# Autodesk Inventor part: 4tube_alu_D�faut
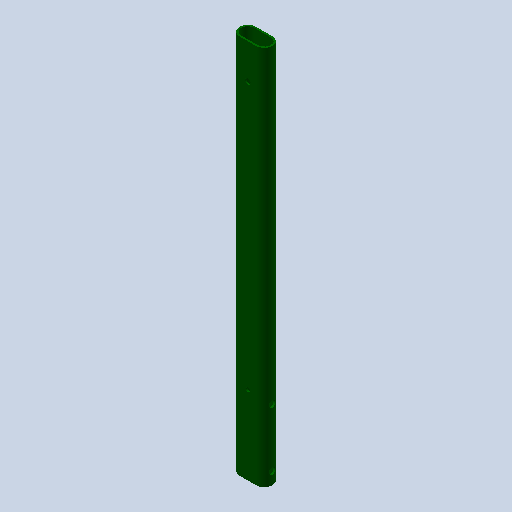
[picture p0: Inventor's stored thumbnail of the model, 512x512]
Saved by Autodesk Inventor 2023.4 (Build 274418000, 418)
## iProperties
Created: 2011-01
Part Number: 4tube_alu_D�faut
Document SubType Name: Modeling
Designer: eric
Density: 1 g/cm^3
Mass: 88.0744 g
Surface Area: 888.505 cm^2
Volume: 88.0744 cm^3
Material: Générique
Appearance: 0,128,0_1
Author: eric
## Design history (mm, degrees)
feature "Base1"
node "Corps solides"
node "Corps surfaciques"
node "Solide1"
